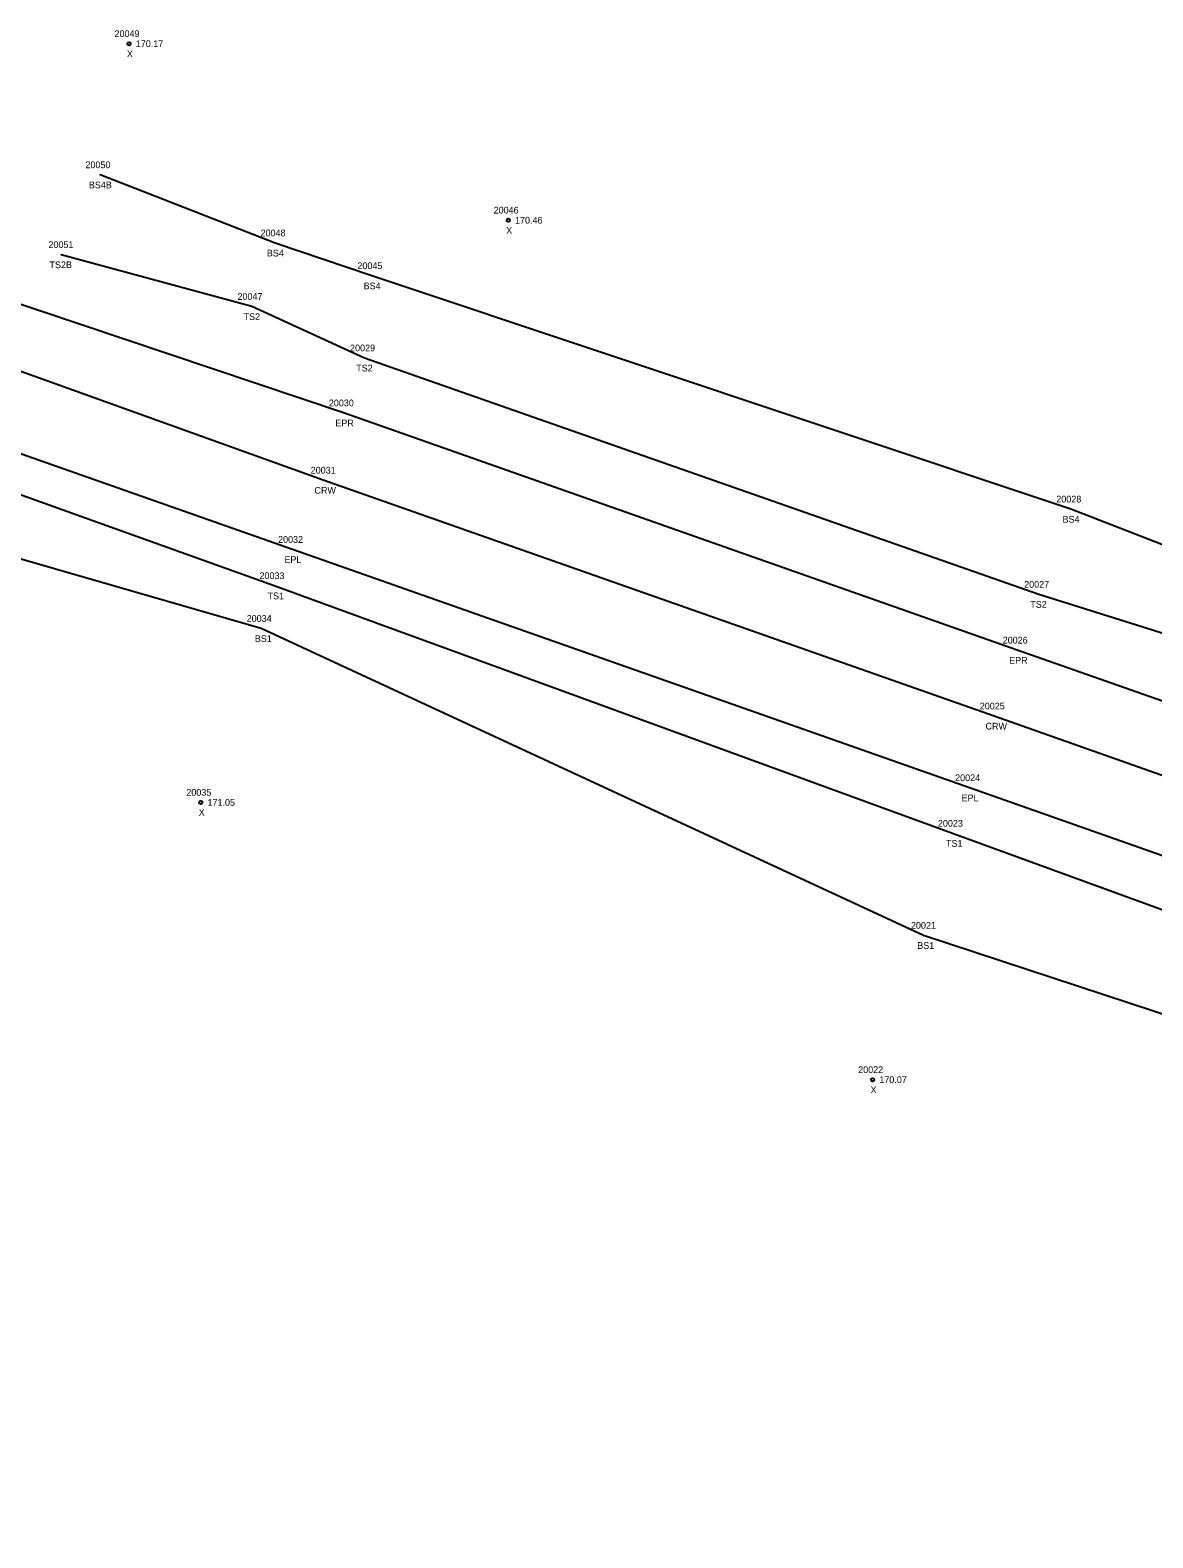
# Model space of a CAD drawing. Extents: x 2054705 to 2055845, y 756616 to 757058.
# Drawn here: x 2055399.2 to 2055566.3, y 756618.3 to 756842.7 of the extents above; entities that cross this region are included whole.
import ezdxf

# ---------------------------------------------------------------- set-up
doc = ezdxf.new("R2010")
doc.units = 0
for name, color, linetype in [('RD_DTM_BkLn1', 7, 'Continuous'), ('RD_DTM_BkLn2', 7, 'Continuous'), ('RD_EX_Road', 7, 'Continuous'), ('RD_EX_Road_txCode', 7, 'Continuous'), ('RD_Sketch8', 7, 'Continuous'), ('RD_SMD_Locator', 7, 'Continuous'), ('RD_SMD_Misc', 7, 'Continuous')]:
    doc.layers.add(name, color=color, linetype=linetype)

msp = doc.modelspace()

# ---------------------------------------------------------------- linework, layer by layer
at = {"layer": 'RD_DTM_BkLn1'}
msp.add_lwpolyline([(2055837.47, 756636.94), (2055735.89, 756672.36), (2055637.56, 756707.1), (2055542.66, 756740.62), (2055442.78, 756775.71), (2055390.81, 756794.36), (2055336.04, 756813.15)], dxfattribs=at)
at = {"layer": 'RD_DTM_BkLn2'}
for points in [[(2055843.75, 756655.39), (2055743.74, 756690.81), (2055644.14, 756736.43), (2055554.04, 756771.41), (2055450.02, 756806.14), (2055435.61, 756811.02), (2055409.58, 756821.16)], [(2055842.3, 756651.42), (2055742.66, 756686.01), (2055645.36, 756728.56), (2055549.27, 756758.74), (2055448.92, 756793.91), (2055432.16, 756801.56), (2055403.75, 756809.28)], [(2055832.49, 756621.52), (2055731.49, 756655.07), (2055631.3, 756688.56), (2055536.43, 756723.17), (2055435.45, 756760.01), (2055382.81, 756778.87), (2055339.17, 756790.36), (2055332.05, 756802.67)], [(2055831.8, 756618.33), (2055729.73, 756648.72), (2055627.89, 756676.46), (2055532.13, 756707.98), (2055433.53, 756753.65), (2055378.99, 756769.4), (2055341.75, 756774.07)]]:
    msp.add_lwpolyline(points, dxfattribs=at)
at = {"layer": 'RD_EX_Road'}
for points in [[(2055840.85, 756646.86), (2055741.4, 756681.66), (2055640.94, 756717.16), (2055546.09, 756750.42), (2055445.8, 756785.73), (2055393.73, 756803.22), (2055338.74, 756823.81), (2055336.04, 756813.15)], [(2055833.7, 756626.43), (2055733.14, 756661.47), (2055633.89, 756696.5), (2055538.99, 756729.94), (2055438.21, 756765.4), (2055385.28, 756784.01), (2055332.05, 756802.67), (2055336.04, 756813.15)]]:
    msp.add_lwpolyline(points, dxfattribs=at)
at = {"layer": 'RD_SMD_Locator'}
for centre, radius in [((2055413.87, 756840.68), 0.25), ((2055409.58, 756821.16), 0.001), ((2055470.32, 756814.41), 0.25), ((2055435.61, 756811.02), 0.001), ((2055403.75, 756809.28), 0.001), ((2055450.02, 756806.14), 0.001), ((2055432.16, 756801.56), 0.001), ((2055448.92, 756793.91), 0.001), ((2055445.8, 756785.73), 0.001), ((2055442.78, 756775.71), 0.001), ((2055554.04, 756771.41), 0.001), ((2055438.21, 756765.4), 0.001), ((2055435.45, 756760.01), 0.001), ((2055549.27, 756758.74), 0.001), ((2055433.53, 756753.65), 0.001), ((2055546.09, 756750.42), 0.001), ((2055542.66, 756740.62), 0.001), ((2055538.99, 756729.94), 0.001), ((2055424.55, 756727.77), 0.25), ((2055536.43, 756723.17), 0.001), ((2055532.13, 756707.98), 0.001), ((2055524.55, 756686.51), 0.25)]:
    msp.add_circle(centre, radius, dxfattribs=at)

# ---------------------------------------------------------------- texts
at = {"layer": 'RD_EX_Road_txCode'}
for s, p in [('20030', (2055443.61, 756786.73)), ('EPR', (2055444.58, 756783.73)), ('20032', (2055436.05, 756766.4)), ('EPL', (2055437, 756763.4)), ('20026', (2055543.91, 756751.42)), ('EPR', (2055544.87, 756748.42)), ('20024', (2055536.83, 756730.94)), ('EPL', (2055537.79, 756727.94))]:
    msp.add_text(s, height=1, dxfattribs=at).set_placement(p)
at = {"layer": 'RD_Sketch8'}
for s, p in [('20049', (2055411.71, 756841.68)), ('170.17', (2055414.87, 756840.18)), ('X', (2055413.55, 756838.68)), ('20046', (2055468.14, 756815.41)), ('170.46', (2055471.32, 756813.91)), ('X', (2055470.01, 756812.41)), ('20035', (2055422.4, 756728.77)), ('X', (2055424.24, 756725.77)), ('171.05', (2055425.55, 756727.27)), ('20022', (2055522.4, 756687.51)), ('170.07', (2055525.55, 756686.01)), ('X', (2055524.24, 756684.51))]:
    msp.add_text(s, height=1, dxfattribs=at).set_placement(p)
at = {"layer": 'RD_SMD_Misc'}
for s, p in [('20050', (2055407.38, 756822.16)), ('BS4B', (2055407.88, 756819.16)), ('20048', (2055433.45, 756812.02)), ('20051', (2055401.87, 756810.28)), ('BS4', (2055434.38, 756809.02)), ('TS2B', (2055402.03, 756807.28)), ('20045', (2055447.86, 756807.14)), ('20047', (2055430.01, 756802.56)), ('BS4', (2055448.79, 756804.14)), ('TS2', (2055430.92, 756799.56)), ('20029', (2055446.77, 756794.91)), ('TS2', (2055447.68, 756791.91)), ('20031', (2055440.91, 756776.71)), ('CRW', (2055441.47, 756773.71)), ('20028', (2055551.89, 756772.41)), ('BS4', (2055552.82, 756769.41)), ('20033', (2055433.29, 756761.01)), ('20027', (2055547.11, 756759.74)), ('TS1', (2055434.49, 756758.01)), ('TS2', (2055548.02, 756756.74)), ('20034', (2055431.38, 756754.65)), ('BS1', (2055432.59, 756751.65)), ('20025', (2055540.5, 756741.62)), ('CRW', (2055541.35, 756738.62)), ('20023', (2055534.27, 756724.17)), ('TS1', (2055535.47, 756721.17)), ('20021', (2055530.26, 756708.98)), ('BS1', (2055531.19, 756705.98))]:
    msp.add_text(s, height=1, dxfattribs=at).set_placement(p)

doc.saveas('drawing.dxf')
